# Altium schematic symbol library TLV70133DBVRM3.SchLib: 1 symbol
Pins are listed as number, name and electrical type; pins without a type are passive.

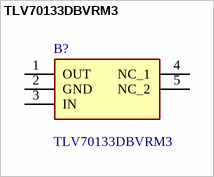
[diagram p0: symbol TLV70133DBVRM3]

## TLV70133DBVRM3
designator B?
LDO Voltage Regulators 150-mA 24-V ultra-low-IQ low-dropout voltage regulator for 3 V and 3.3 V; Manufacturer_Name: Texas Instruments; Geometry.Height: 1.45mm
footprint SOT95P280X145-5N
pins: 1 OUT, 2 GND, 3 IN, 4 NC_1, 5 NC_2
